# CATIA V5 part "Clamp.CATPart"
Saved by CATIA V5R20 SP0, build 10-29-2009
Part number: Adapter
Bounding box of the stored display mesh (mm): x -19.934 to 93.312, y -54.494 to -29.494, z 0 to 25
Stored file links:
  C:\Users\user\SkyDrive\Stuff\cad\Instructables\Hand adapter\CATIA V5, STEP ,IGES Files\Clamp.CATPart
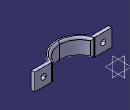
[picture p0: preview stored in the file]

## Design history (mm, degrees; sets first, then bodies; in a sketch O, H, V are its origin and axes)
Body1 (main body)
  Sketch1 on xy-plane, origin (0, 0, 0), H (1, 0, 0), V (0, 1, 0)
    point P1 (-19.9339, -29.4941)
    line L1 (-19.9339, -29.4941) -> (5.0661, -29.4941)
    line L2 (5.0661, -34.4941) -> (-19.9339, -34.4941)
    line L3 (-19.9339, -34.4941) -> (-19.9339, -29.4941)
    point P2 (5.0661, -29.4941)
    point P3 (5.0661, -34.4941)
    point P4 (-19.9339, -34.4941)
    arc A1 centre (36.6888, -19.4941) radius 30 from (8.4046, -29.4941) to (36.6888, -49.4941) ccw
    point P5 (36.6888, -19.4941)
    arc A2 centre (36.6888, -19.4941) radius 35 from (5.0661, -34.4941) to (36.6888, -54.4941) ccw
    construction line L4 (36.6888, 45.3755) -> (36.6888, -65.3973)
    point P8 (36.6888, -54.4941)
    point P9 (36.6888, -49.4941)
    line L5 (5.0661, -29.4941) -> (8.4046, -29.4941)
    point P10 (8.4046, -29.4941)
    point P11 (93.3116, -29.4941)
    point P12 (93.3116, -34.4941)
    line L6 (93.3116, -34.4941) -> (93.3116, -29.4941)
    point P13 (68.3116, -29.4941)
    line L7 (93.3116, -29.4941) -> (68.3116, -29.4941)
    point P14 (68.3116, -34.4941)
    line L8 (68.3116, -34.4941) -> (93.3116, -34.4941)
    point P15 (36.6888, -54.4941)
    arc A3 centre (36.6888, -19.4941) radius 35 from (68.3116, -34.4941) to (36.6888, -54.4941) cw
    point P17 (36.6888, -49.4941)
    point P18 (64.9731, -29.4941)
    arc A4 centre (36.6888, -19.4941) radius 30 from (64.9731, -29.4941) to (36.6888, -49.4941) cw
    line L9 (68.3116, -29.4941) -> (64.9731, -29.4941)
    length L2 = 25
    radius A1 = 30
    distance A1 A2 = 5
    distance L1 P5 = 10
    distance P2 P3 = 5
    horizontal: L1 H, L2 H, L5 H
    vertical: L3 V, L4 V
    coincidence: L4 P8, L4 P9, P8 P15, P9 P17
    symmetry: P1 P11 L4, P4 P12 L4, L3 L6 L4, P2 P13 L4, L1 L7 L4, P3 P14 L4, L2 L8 L4, P8 P15 L4, A2 A3 L4, P9 P17 L4, P10 P18 L4, A1 A4 L4, L5 L9 L4
  Pad1: profile Sketch1, direction (0, 0, 1), length 25
  Fillet1: radius 3, on edge [start face of Pad1 | face of Pad1 from Sketch1.A4]; edge [start face of Pad1 | face of Pad1 from Sketch1.A1]; edge [face of Pad1 from Sketch1.L5 | face of Pad1 from Sketch1.A1]; edge [face of Pad1 from Sketch1.A1 | end face of Pad1]; edge [face of Pad1 from Sketch1.A4 | end face of Pad1]; edge [face of Pad1 from Sketch1.A4 | face of Pad1 from Sketch1.L9]
  Sketch2 on face of Pad1 from Sketch1.L1, origin (-11.9013, -29.4941, 20.8768), H (1, 0, 0), V (0, 0, -1)
    point P1 (4.4674, 8.3768)
    reference projected line E1 (-8.0326, 20.8768) -> (-8.0326, -4.1232) from edge [face of Pad1 from Sketch1.L3 | face of Pad1 from Sketch1.L1]
    reference projected line E2 (16.9674, 20.8768) -> (16.9674, -4.1232) from edge [face of Pad1 from Sketch1.L1 | face of Pad1 from Sketch1.L5]
    reference projected line E3 (16.9674, -4.1232) -> (-8.0326, -4.1232) from edge [face of Pad1 from Sketch1.L1 | end face of Pad1]
    reference projected line E4 (16.9674, 20.8768) -> (-8.0326, 20.8768) from edge [start face of Pad1 | face of Pad1 from Sketch1.L1]
    equidistance: E1 E2 P1, E3 E4 P1
  Hole1: placed by Sketch2, at (-7.4339, -29.4941, 12.5) direction (0, -1, 0), diameter 8, through (limit type 6)
  Sketch3 on face of Pad1 from Sketch1.L7, origin (79.5127, -29.4941, 13.799), H (1, 0, 0), V (0, 0, -1)
    point P1 (0.6533, 1.299)
    reference projected line E1 (-12.4923, -11.0066) -> (-12.4923, 13.6045) from edge [face of Pad1 from Sketch1.L9 | face of Fillet1]
    reference projected line E2 (13.7989, 13.799) -> (13.7989, -11.201) from edge [face of Pad1 from Sketch1.L7 | face of Pad1 from Sketch1.L6]
    reference projected line E3 (13.7989, -11.201) -> (-11.2011, -11.201) from edge [face of Pad1 from Sketch1.L7 | end face of Pad1]
    reference projected line E4 (13.7989, 13.799) -> (-11.2011, 13.799) from edge [start face of Pad1 | face of Pad1 from Sketch1.L7]
    equidistance: E1 E2 P1, E3 E4 P1
  Hole2: placed by Sketch3, at (80.166, -29.4941, 12.5) direction (0, -1, 0), diameter 8, through (limit type 6)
